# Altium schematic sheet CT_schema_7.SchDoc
size 274 x 160 mm
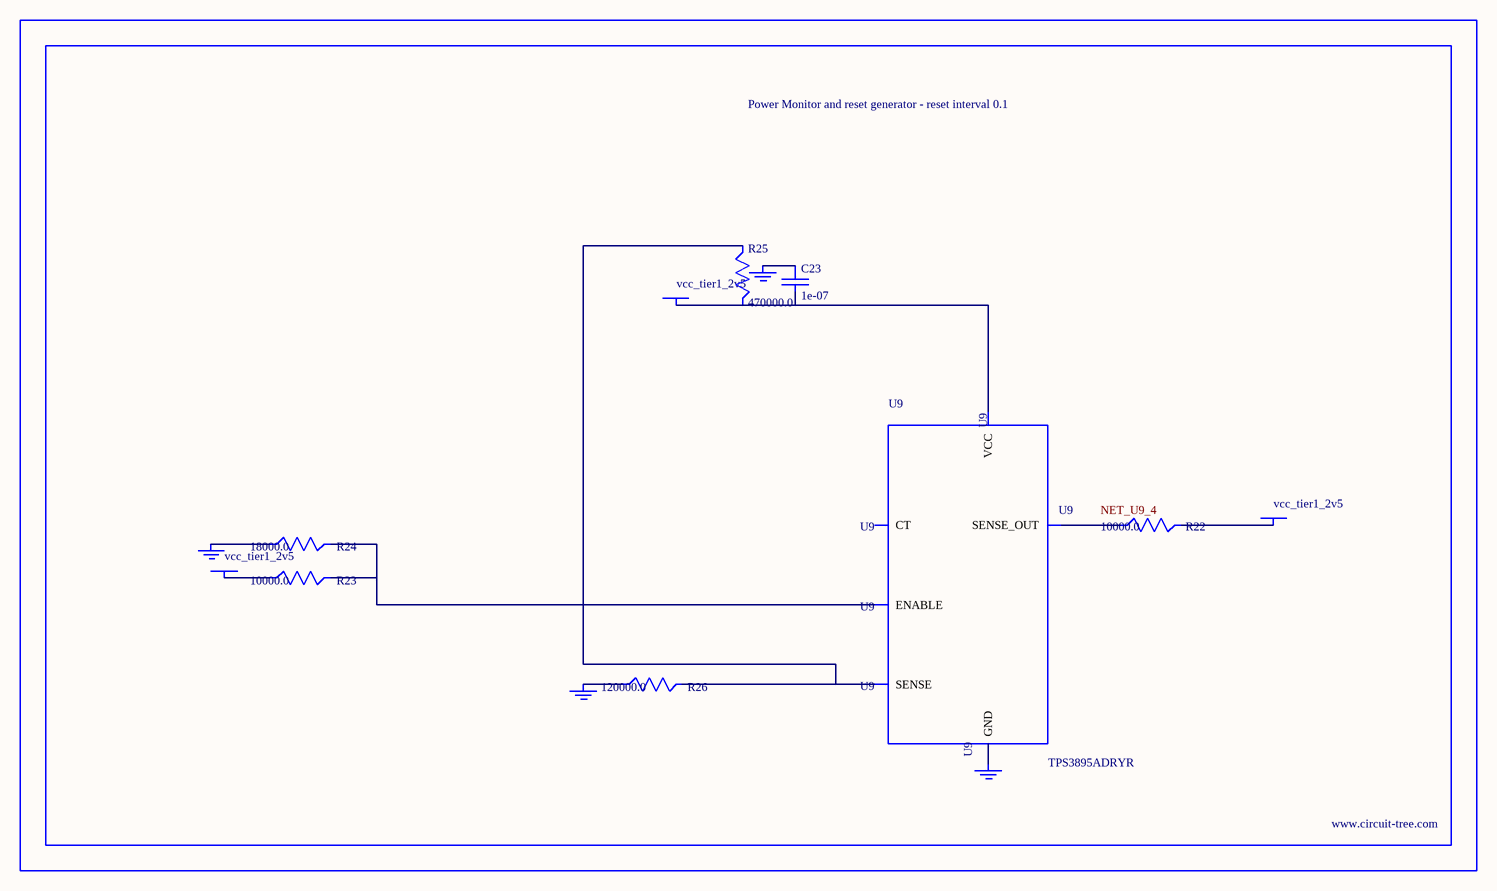
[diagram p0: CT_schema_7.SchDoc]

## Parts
BORDER6  (no value)
C23  1e-07  [C0402]
GND_INSTANCE_6_0  (no value)
GND_INSTANCE_6_1  (no value)
GND_INSTANCE_6_2  (no value)
GND_INSTANCE_6_3  (no value)
POWER_INSTANCE_6_0  vcc_tier1_2v5
POWER_INSTANCE_6_1  vcc_tier1_2v5
POWER_INSTANCE_6_2  vcc_tier1_2v5
R22  10000.0  [R0603]
R23  10000.0  [R0603]
R24  18000.0  [R0603]
R25  470000.0  [R0603]
R26  120000.0  [R0603]
U9  TPS3895ADRYR  [SON-6]

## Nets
NetC23_1: C23.1 GND_INSTANCE_6_2.0(GND)
NetC23_2: C23.2 POWER_INSTANCE_6_2.0(PWR) R25.2 U9.6(VCC)
NetGND_INSTANCE_6_0_0: GND_INSTANCE_6_0.0(GND) R24.1
NetGND_INSTANCE_6_1_0: GND_INSTANCE_6_1.0(GND) R26.1
NetGND_INSTANCE_6_3_0: GND_INSTANCE_6_3.0(GND) U9.2(GND)
NetPOWER_INSTANCE_6_0_0: POWER_INSTANCE_6_0.0(PWR) R23.1
NetPOWER_INSTANCE_6_1_0: POWER_INSTANCE_6_1.0(PWR) R22.2
NetR22_1: R22.1 U9.4(SENSE_OUT)
NetR23_2: R23.2 R24.2 U9.1(ENABLE)
NetR25_1: R25.1 R26.2 U9.3(SENSE)

Not connected (* = marked no-connect by the designer): U9 5(CT)

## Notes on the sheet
- Labels drawn without touching a wire or pin: NET_U9_4

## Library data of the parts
BORDER6 = BORDER_PAGE6
C23 = C0402C104K3RACTU
GND_INSTANCE_6_0-GND_INSTANCE_6_3 = GND
POWER_INSTANCE_6_0-POWER_INSTANCE_6_2 = PWR
R22 R23 = RC0603JR-0710KL
R24 = RC0603JR-0718KL
R25 = RC0603JR-07470KL
R26 = RC0603JR-07120KL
